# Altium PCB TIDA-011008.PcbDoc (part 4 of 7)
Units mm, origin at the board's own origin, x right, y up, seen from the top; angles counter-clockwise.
Board outline 252 x 205 mm, 4 copper layers (Top Layer, Inner Layer 1, Inner Layer 2, Bottom Layer), stack 1.926 mm thick; 517 components, 293 nets, 1426 pads, 1855 vias.
Unrouted connection lines stored in the file: 4.
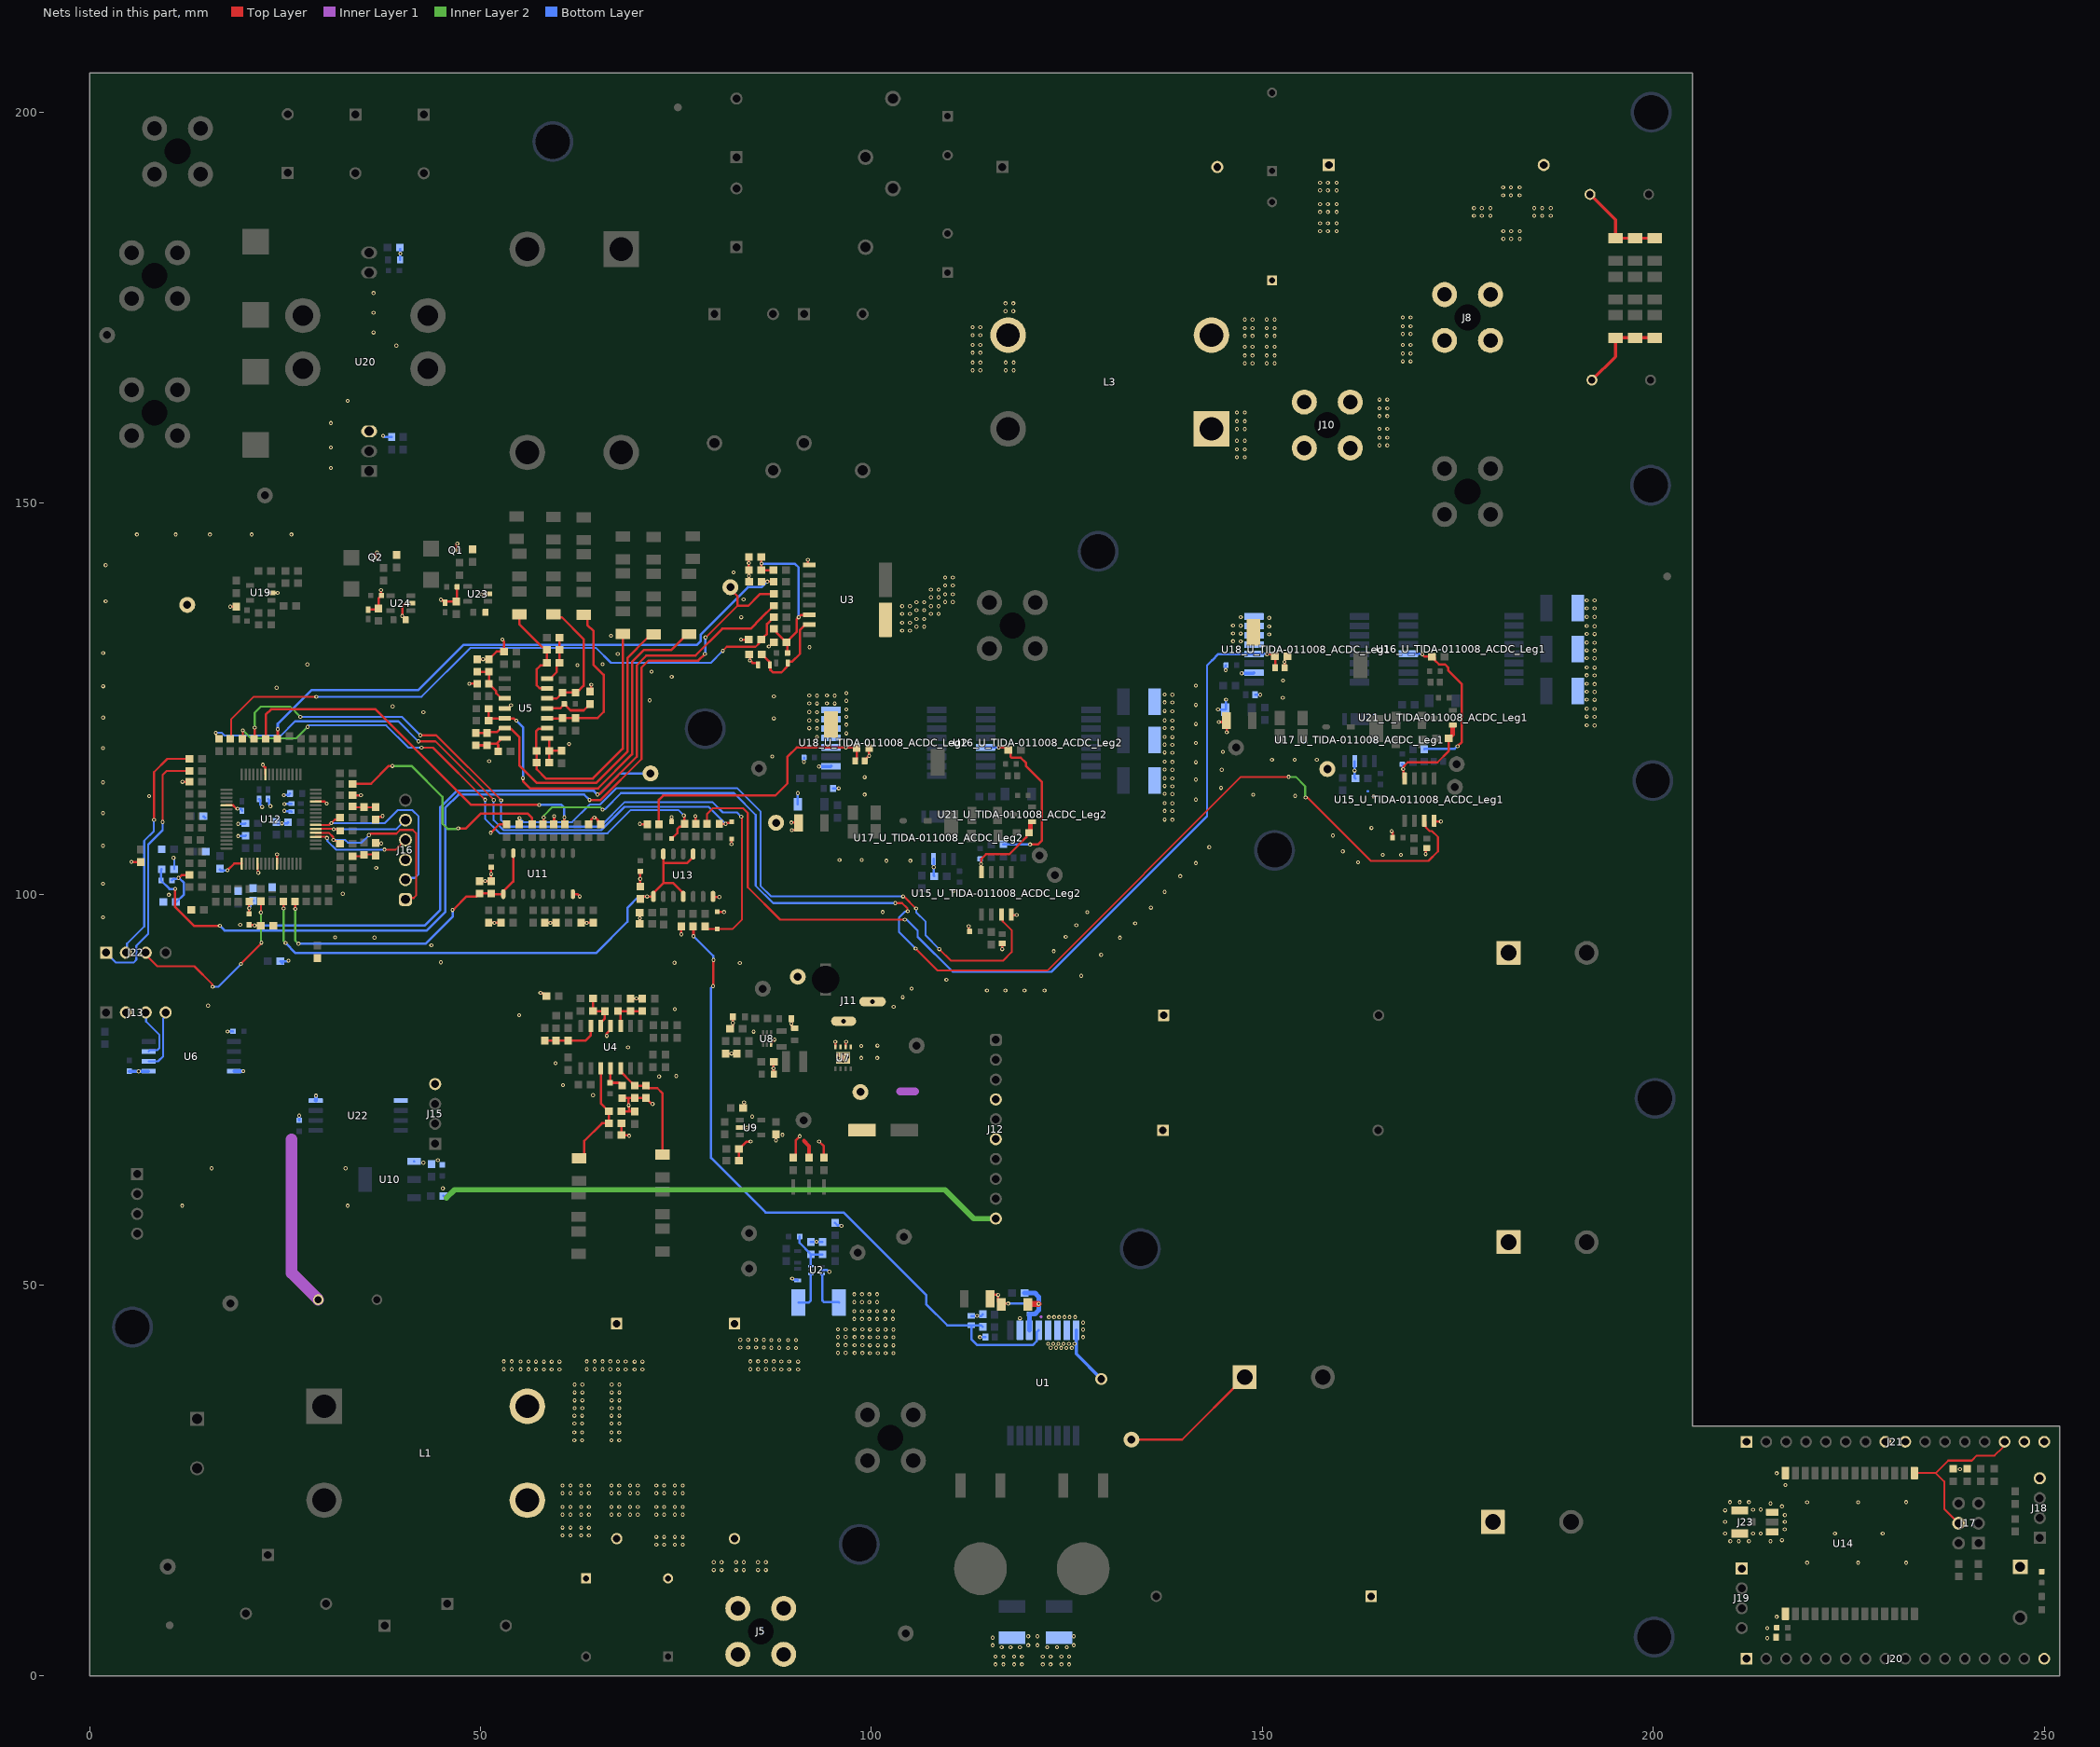
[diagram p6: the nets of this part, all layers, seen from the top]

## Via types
v1: diameter 0.508, hole 0.254, Top Layer to Bottom Layer, tented both sides, 1852 vias
v2: diameter 1.5/1.5/1.5/1.5 (per signal layer), hole 1, Top Layer to Bottom Layer, 2 vias
v3: diameter 0.508, hole 0.254, Top Layer to Bottom Layer, 1 vias

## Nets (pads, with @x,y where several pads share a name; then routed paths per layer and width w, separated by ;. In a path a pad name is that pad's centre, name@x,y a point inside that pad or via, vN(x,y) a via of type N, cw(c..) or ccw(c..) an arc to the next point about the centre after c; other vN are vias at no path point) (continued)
DC_Bus-: C1.1 C2.1 C3.1 C4.1 C5.1 C6.1 C7.2 C9.2 C10.2 C11.1 C14.1 C15.1 C16.1 C17.2 C18.2 C21.2 C22.2 C23.2 C28.1 C29.1 C32.1 C33.2 C34.2 C35.2 C36.2 C37.1 C38.1 C39.1 C40.2 C41.2 C42.1 C43.1 C44.2 C45.1 C46.2 C47.2 C48.1 C49.2 C53.1 C54.1 C55.1 C60.1 C61.1 C62.1 C65.2 C67.2 C69.2 C71.1 C72.1 C75.2 C76.2 C77.1 C78.1 C79.2 C80.2 C81.1 C82.2 C83.2 C84.1 C85.2 C86.2 C87.2 C88.2 C89.1 C90.2 C91.2 C92.1 C93.1 C94.1 C95.1 C96.2 C97.2 C98.2 C99.2 C100.2 C101.2 C102.2 C103.2 C104.2 C108_U_TIDA-011008_ACDC_Leg1.1 C108_U_TIDA-011008_ACDC_Leg2.1 C116_U_TIDA-011008_ACDC_Leg1.2 C116_U_TIDA-011008_ACDC_Leg2.2 C118_U_TIDA-011008_ACDC_Leg1.2 C118_U_TIDA-011008_ACDC_Leg2.2 C119_U_TIDA-011008_ACDC_Leg1.2 C119_U_TIDA-011008_ACDC_Leg2.2 C120_U_TIDA-011008_ACDC_Leg1.2 C120_U_TIDA-011008_ACDC_Leg2.2 C121_U_TIDA-011008_ACDC_Leg1.2 C121_U_TIDA-011008_ACDC_Leg2.2 C122_U_TIDA-011008_ACDC_Leg1.2 C122_U_TIDA-011008_ACDC_Leg2.2 C123_U_TIDA-011008_ACDC_Leg1.2 C123_U_TIDA-011008_ACDC_Leg2.2 C124_U_TIDA-011008_ACDC_Leg1.2 C124_U_TIDA-011008_ACDC_Leg2.2 C125_U_TIDA-011008_ACDC_Leg1.1 C125_U_TIDA-011008_ACDC_Leg2.1 C126_U_TIDA-011008_ACDC_Leg1.1 C126_U_TIDA-011008_ACDC_Leg2.1 C127_U_TIDA-011008_ACDC_Leg1.1 C127_U_TIDA-011008_ACDC_Leg2.1 C128.1 C129.1 C130.2 C132.1 C134.2 C135.2 C136.1 C137.2 C138.1 C139.1 C140.1 C141.1 D10.2 D11.2 D12.2 J11.2 J11.3 J12.4 J12.6 J16.3 Q1.2@46.898,143.989 Q2.2@36.614,143.095 R5.1 R7.2 R10.1 R28.1 R36.1 R37.1 R50.2 R51.1 R52.1 R53.2 R54.1 R83.2 R92.1 R93.1 R98.2 R99.1 R100.1 R104.1 R105.1 R106.1 R107.2 R128.1 R129.1 R130.1 R131.1 R137.2 R144.1 R161.2 R181_U_TIDA-011008_ACDC_Leg1.1 R181_U_TIDA-011008_ACDC_Leg2.1 R192.2 R193.2 TP2.1 TP5.1 TP23.1 TP24.1 TP31_U_TIDA-011008_ACDC_Leg1.1 TP31_U_TIDA-011008_ACDC_Leg2.1 TP32_U_TIDA-011008_ACDC_Leg1.1 TP32_U_TIDA-011008_ACDC_Leg2.1 U1.10 U1.13 U1.14 U1.15 U1.16 U2.2 U2.3 U3.3 U4.11 U5.11 U6.4 U7.5 U7.6 U7.7 U7.8 U7.9 U8.3 U9.2 U11.8 U12.5 U12.17 U12.21 U12.26 U12.45 U12.58 U13.7 U15_U_TIDA-011008_ACDC_Leg1.4 U15_U_TIDA-011008_ACDC_Leg2.4 U17_U_TIDA-011008_ACDC_Leg1.3 U17_U_TIDA-011008_ACDC_Leg2.3 U18_U_TIDA-011008_ACDC_Leg1.10 U18_U_TIDA-011008_ACDC_Leg1.13 U18_U_TIDA-011008_ACDC_Leg1.14 U18_U_TIDA-011008_ACDC_Leg1.15 U18_U_TIDA-011008_ACDC_Leg1.16 U18_U_TIDA-011008_ACDC_Leg2.10 U18_U_TIDA-011008_ACDC_Leg2.13 U18_U_TIDA-011008_ACDC_Leg2.14 U18_U_TIDA-011008_ACDC_Leg2.15 U18_U_TIDA-011008_ACDC_Leg2.16 U19.2 U20.3 U22.4 U23.2 U24.2 | length 220.6
  Top Layer w0.254: v1(17.989,136.774) 18.723,136.774 C130.2@18.747,136.75 ; U12.21@21.465,103.902 21.488,103.879 21.488,102.906 21.588,102.807 v1(21.588,102.74) ; U19.2@23.275,138.544 v1(24.058,138.544) ; Q2.2@36.614,143.095 36.616,143.097 36.616,143.501 36.769,143.654 v1(36.769,143.723) ; Q1.2@46.898,143.989 46.898,144.679 v1(47.039,144.819)
  Top Layer w0.3: v1(5.345,104.129) 6.527,104.129 C62.1@6.545,104.112 ; v1(11.881,114.37) 12.786,114.37 C102.2@12.79,114.365 ; C61.1@13.007,98.028 C61.1@13.035,97.999 ; U12.5@17.515,111.352 18.374,111.352 18.766,110.96 18.888,110.96 v1(18.927,110.922) ; v1(17.645,103.052) 18.495,103.902 U12.17@19.465,103.902 ; v1(22.155,116.555) 22.194,116.516 22.194,116.451 22.465,116.179 U12.58@22.465,115.302 ; U12.26@23.965,103.902 23.965,105.079 v1(23.978,105.092) ; U12.45@28.915,111.852 30.06,111.852 30.312,111.601 v1(30.328,111.601) ; R161.2@33.646,112.65 v1(34.717,112.65) ; C40.2@35.634,136.396 36.793,136.396 R36.1@36.951,136.554 36.951,137.809 37.32,138.178 C28.1@37.32,138.203 37.269,138.254 v1(37.269,138.891) ; R193.2@36.586,106.531 36.633,106.484 v1(37.311,106.484) ; R192.2@36.588,109.552 36.588,109.577 36.913,109.902 37.378,109.902 v1(37.478,110.002) ; C138.1@40.424,135.086 40.424,135.161 v1(40,135.586) 40,136.774 40.278,137.052 40.951,137.052 U24.2@41.101,137.202 ; v1(44.938,137.674) 44.978,137.634 45.111,137.634 45.227,137.518 45.327,137.518 45.477,137.368 C33.2@45.477,137.268 ; C33.2@45.627,137.426 R28.1@46.898,137.426 47.015,137.544 C29.1@47.015,139.306 ; v1(48.575,126.914) C43.1@49.598,126.914 ; R50.2@49.598,130.051 v1(50.323,130.051) 51.093,130.051 C45.1@51.098,130.056 51.098,130.081 52.06,131.043 C48.1@52.993,131.043 52.993,132.322 52.797,132.518 v1(52.797,132.572) ; C129.1@49.868,101.685 v1(50.593,101.685) R107.2@51.368,101.685 v1(51.368,102.572) C84.1@51.368,103.46 ; v1(50.12,138.362) 50.935,138.362 U23.2@50.965,138.393 ; R128.1@51.047,96.335 v1(51.772,96.335) C85.2@52.643,96.335 ; v1(51.317,107.852) 52.399,108.935 C83.2@53.368,108.935 ; U5.11@53.101,123.764 53.518,123.764 53.911,124.156 v1(53.911,124.164) ; v1(57.671,87.399) 57.728,87.399 57.825,87.301 58.096,87.301 C137.2@58.421,86.976 ; R129.1@58.253,96.335 v1(58.957,96.335) C86.2@59.682,96.335 ; C82.2@59.368,108.935 59.421,108.987 v1(59.421,109.965) ; v1@61.342,119.069 v1(61.342,119.208) ; U11.8@61.813,100.01 62.402,100.01 v1(62.706,99.706) ; R130.1@62.868,96.335 C87.2@64.406,96.335 ; R131.1@63.831,108.935 64.156,109.26 64.156,109.516 64.414,109.774 v1@64.53,109.774 ; C49.2@64.001,125.925 64.171,126.096 v1(64.171,126.796) ; v1(64.569,109.813) v1@64.53,109.774 ; C88.2@65.368,108.935 65.043,109.26 65.043,109.462 64.731,109.774 v1@64.53,109.774 ; v1(66.154,81.881) 66.154,82.182 66.654,82.682 U4.11@66.654,83.168 ; R51.1@68.024,70.718 R54.1@68.024,69.193 68.891,69.193 68.978,69.107 v1(69.032,69.107) ; C46.2@68.024,72.218 69.036,72.218 ; C42.1@68.104,73.918 68.829,73.918 ; R83.2@69.22,86.657 v1(69.945,86.657) C60.1@70.714,86.657 ; R53.2@69.761,72.218 69.036,72.218 ; C90.2@70.382,96.206 v1(70.382,96.931) R144.1@70.382,97.635 ; v1(70.382,108.989) 70.416,108.955 C96.2@71.319,108.955 ; R137.2@70.432,100.981 v1(70.432,101.956) C89.1@70.432,102.931 ; v1(72.016,73.176) 71.978,73.214 71.872,73.214 71.189,73.896 C47.2@71.189,73.921 R52.1@69.761,73.921 69.757,73.918 68.829,73.918 ; v1(74.442,109.85) 74.442,109.303 D11.2@74.452,109.294 ; C91.2@75.669,95.881 75.692,95.857 v1(75.692,94.864) ; v1(77.486,109.982) 77.519,109.949 C101.2@77.519,108.981 ; U13.7@79.742,99.706 79.817,99.631 v1(80.557,99.631) ; D10.2@80.288,97.742 81.125,97.742 v1(81.154,97.713) v1@81.183,97.685 ; C81.1@81.383,79.615 v1(82.108,79.615) 82.804,79.615 R106.1@82.808,79.619 ; R105.1@81.933,82.808 81.958,82.808 82.283,83.133 v1(82.283,83.533) C79.2@82.283,84.308 ; v1(82.108,106.393) 82.112,106.397 D12.2@82.112,107.081 ; C78.1@83.058,65.908 R104.1@83.058,67.408 83.083,67.408 83.993,68.319 84.518,68.319 v1(84.558,68.358) ; U9.2@83.183,70.158 v1(84.058,70.158) ; v1(83.328,132.562) 84.289,132.562 C38.1@84.295,132.568 ; C71.1@83.608,72.658 83.708,72.759 v1(83.708,73.383) ; v1(83.654,137.703) v1@83.684,137.703 ; C35.2@84.339,143.144 84.317,143.122 v1(84.317,142.335) 84.317,141.481 84.347,141.451 v1(84.347,140.705) C39.1@84.347,139.98 ; C41.2@84.378,130.685 84.46,130.602 v1(84.46,129.878) 84.515,129.878 84.81,129.583 85.41,129.583 85.51,129.483 R37.1@85.51,129.327 ; v1(86.885,131.682) 86.923,131.721 86.994,131.721 87.491,132.218 C34.2@87.516,132.218 ; U8.3@87.158,80.785 87.158,80.97 87.595,81.407 v1(87.628,81.407) ; C75.2@87.495,77.231 87.497,77.233 87.497,77.706 v1(87.479,77.725) 87.479,78.542 C77.1@87.52,78.583 ; v1(87.808,68.522) C72.1@87.808,69.272 ; v1(89.769,109.16) 90.676,109.16 C123_U_TIDA-011008_ACDC_Leg2.2@90.697,109.14 90.697,108.594 90.297,108.194 v1(89.812,108.194) ; C76.2@89.775,84.058 v1(89.775,83.433) 89.775,83.191 90.108,82.858 C80.2@90.183,82.858 ; R100.1@90.012,66.295 90.337,66.62 90.337,68.542 90.831,69.036 v1(90.831,69.043) ; v1(91.876,142.756) 91.876,142.236 92.026,142.086 U3.3@92.053,142.086 ; v1(93.311,68.373) 93.933,67.752 R98.2@93.933,66.295 ; v1(95.386,81.118) 95.408,81.096 U7.8@95.408,80.479 ; U7.6@96.708,80.479 96.708,81.062 v1(96.763,81.118) ; C127_U_TIDA-011008_ACDC_Leg2.1@99.14,117.053 99.14,117.128 v1(99.714,117.702) R181_U_TIDA-011008_ACDC_Leg2.1@99.714,118.683 ; v1(112.438,95.908) 112.438,95.362 C108_U_TIDA-011008_ACDC_Leg2.1@112.567,95.233 ; C9.2@115.175,48.275 115.175,48.576 115.374,48.775 116.176,48.775 v1(116.209,48.742) 116.215,48.736 116.215,47.925 C10.2@116.615,47.525 116.734,47.644 v1(117.501,47.644) ; v1(116.742,92.974) C116_U_TIDA-011008_ACDC_Leg2.2@116.742,93.708 ; U15_U_TIDA-011008_ACDC_Leg2.4@117.897,97.408 117.976,97.33 v1(118.581,97.33) ; TP2.1@133.049,30.25 TP2.1@133.266,30.25 139.75,30.25 C3.1@147.75,38.25 ; v1(144.444,122.018) 145.236,122.018 C123_U_TIDA-011008_ACDC_Leg1.2@145.416,122.198 145.455,122.159 v1(145.455,120.699) ; C127_U_TIDA-011008_ACDC_Leg1.1@152.844,128.95 v1(152.844,129.704) 152.844,130.075 152.848,130.079 152.848,130.104 153.173,130.429 R181_U_TIDA-011008_ACDC_Leg1.1@153.198,130.429 ; v1(166.547,108.052) 166.662,107.937 C108_U_TIDA-011008_ACDC_Leg1.1@166.662,107.229 ; v1(170.895,105.13) 170.895,105.771 C116_U_TIDA-011008_ACDC_Leg1.2@171.03,105.907 ; U15_U_TIDA-011008_ACDC_Leg1.4@171.992,109.404 172.101,109.295 v1(172.837,109.295) ; 68.829,73.918 68.956,73.792 v1(68.956,73.006) 68.994,72.967 68.994,72.508 69.036,72.467 69.036,72.218
  Top Layer w0.5: 91.372,68.455 91.372,68.453 92.034,67.791 R99.1@92.033,66.295
  Inner Layer 1 w0.4: 121.671,45.962 121.717,45.916
  Inner Layer 1 w1: 103.676,74.768 105.608,74.768
  Inner Layer 1 w1.5: 25.835,68.619 25.835,51.553 C7.2@29.25,48.138
  Bottom Layer w0.254: v1(10.74,104.636) 10.824,104.552 C37.1@10.824,103.203
  Bottom Layer w0.3: C54.1@14.574,109.965 C54.1@14.795,109.744 ; C128.1@16.665,103.165 16.778,103.052 v1(17.645,103.052) ; v1(17.656,82.451) 17.668,82.463 18.336,82.463 C65.2@18.348,82.475 ; v1(18.927,110.922) 18.965,110.884 19.354,110.884 19.504,110.734 C93.1@19.504,110.677 ; v1(19.014,107.434) 19.922,107.434 C98.2@19.965,107.477 ; v1(19.014,108.992) 19.876,108.992 C97.2@19.94,109.056 ; C100.2@21.665,112.177 21.815,112.027 21.815,111.474 22.083,111.206 v1(22.083,111.152) ; C92.1@22.84,112.177 22.99,112.027 22.99,111.457 23.14,111.307 v1(23.14,111.253) ; C103.2@23.895,109.215 24.047,109.064 v1(24.6,109.064) 25.264,109.064 C104.2@25.39,109.19 ; C120_U_TIDA-011008_ACDC_Leg2.2@24.676,91.145 C120_U_TIDA-011008_ACDC_Leg2.2@24.399,91.421 25.377,91.421 v1(25.443,91.487) ; v1(24.835,112.65) 24.873,112.688 25.447,112.688 C95.1@25.638,112.879 ; v1(24.896,110.665) 24.934,110.627 25.741,110.627 C99.2@25.815,110.552 ; v1(24.924,111.527) 24.949,111.552 25.79,111.552 C94.1@25.815,111.577 ; v1(26.808,71.685) 26.815,71.678 26.815,71.086 C67.2@26.822,71.079 ; v1(37.553,158.614) 37.607,158.614 37.766,158.454 C134.2@38.648,158.454 ; C135.2@39.717,181.11 39.731,181.125 39.731,181.908 v1(39.746,181.923) 39.746,182.489 C136.1@39.735,182.5 ; v1(89.862,50.857) 90.01,50.709 90.475,50.709 R10.1@90.575,50.609 ; C124_U_TIDA-011008_ACDC_Leg2.2@90.592,111.505 v1(90.592,112.93) ; v1(91.378,116.917) C125_U_TIDA-011008_ACDC_Leg2.1@91.378,117.486 ; C21.2@92.26,55.542 v1(92.985,55.542) C22.2@93.74,55.542 ; U2.3@93.74,51.442 93.733,51.442 93.733,48.044 93.95,47.827 95.829,47.827 R7.2@95.865,47.79 ; U2.2@93.74,51.942 94.331,51.942 94.562,51.711 v1(94.616,51.711) ; C126_U_TIDA-011008_ACDC_Leg2.1@95.1,113.539 v1(95.823,113.539) ; C23.2@95.35,57.992 95.35,57.967 95.675,57.642 96.056,57.642 96.115,57.583 v1(96.171,57.583) ; U17_U_TIDA-011008_ACDC_Leg2.3@107.97,104.508 v1(107.97,103.446) 107.97,102.384 C118_U_TIDA-011008_ACDC_Leg2.2@108.055,102.299 ; C15.1@112.775,46.075 v1(113.525,46.075) 114.05,46.075 R5.1@114.25,46.275 ; v1(113.887,43.35) C14.1@114.585,43.35 ; v1@117.48,47.623 v1(117.501,47.644) 117.523,47.666 C11.1@120.2,47.666 ; v1(144.34,123.623) C124_U_TIDA-011008_ACDC_Leg1.2@145.274,123.623 145.363,123.712 v1(145.363,124.879) ; v1(145.312,128.658) 145.312,129.228 C125_U_TIDA-011008_ACDC_Leg1.1@145.363,129.279 ; C126_U_TIDA-011008_ACDC_Leg1.1@149.078,125.527 149.098,125.507 v1(149.726,125.507) ; U17_U_TIDA-011008_ACDC_Leg1.3@161.814,117.004 161.814,114.88 C118_U_TIDA-011008_ACDC_Leg1.2@161.899,114.795 ; 163.499,113.195 163.524,113.195 ; v1@164.198,112.52 v1(164.207,112.52)
  Bottom Layer w0.4: v1(93.299,116.32) 93.319,116.339 94.811,116.339 U18_U_TIDA-011008_ACDC_Leg2.10@94.845,116.373 ; U1.16@126.2,44.25 126.2,41.201 v2(129.403,37.998) ; v1(147.364,128.245) 148.866,128.245 U18_U_TIDA-011008_ACDC_Leg1.10@148.938,128.317
  Bottom Layer w0.5: U6.4@18.515,77.359 18.523,77.367 19.67,77.367 v1(19.671,77.368) ; U22.4@28.93,73.605 28.963,73.638 v1(28.963,74.233)
  other v1: 115.875,1.505 116.875,1.505 118.25,1.505 119.25,1.505 121.925,1.505 122.925,1.505 124.3,1.505 125.3,1.505 115.875,2.5 116.875,2.5 118.25,2.5 119.25,2.5 121.925,2.5 122.925,2.5 124.3,2.5 125.3,2.5 116.665,3.702 117.801,3.702 119,3.702 122.5,3.702 123.75,3.702 125,3.702 115.5,3.953 120.064,3.953 121.25,3.953 125.875,3.953 115.5,4.923 120.064,5.1 121.25,5.1 125.875,5.1 99.817,41.308 100.817,41.308 101.826,41.307 102.826,41.307 97.851,41.328 98.851,41.328 95.714,41.342 96.714,41.342 124.936,41.974 122.938,41.99 123.611,41.994 124.264,41.98 125.629,41.98 99.817,42.303 100.817,42.303 101.826,42.302 102.826,42.302 97.851,42.323 98.851,42.323 95.714,42.338 96.714,42.338 122.612,42.496 123.273,42.496 123.925,42.496 124.585,42.496 125.26,42.496 125.983,42.496 99.817,43.331 100.817,43.331 101.826,43.329 102.826,43.329 95.714,43.365 96.714,43.365 97.851,43.351 98.851,43.351 127.075,43.35 99.817,44.326 100.817,44.326 101.826,44.325 102.826,44.325 127.071,44.314 95.714,44.36 96.714,44.36 97.851,44.346 98.851,44.346 127.075,45.215 97.8,45.674 98.8,45.674 99.734,45.674 100.734,45.674 101.763,45.674 102.763,45.674 119,45.76 122.707,45.916 123.368,45.916 124.02,45.916 124.68,45.916 125.355,45.916 126.079,45.916 97.8,46.67 98.8,46.67 99.734,46.67 100.734,46.67 101.763,46.67 102.763,46.67 97.801,47.839 98.801,47.839 99.737,47.839 100.737,47.839 97.801,48.834 98.801,48.834 99.737,48.834 100.737,48.834 88.623,69.223 84.745,71.564 64.397,74.307 60.546,75.576 72.849,76.691 75.051,76.743 59.604,78.384 96.383,78.579 98.692,79.058 100.751,79.058 95.758,79.079 97.008,79.079 96.383,79.579 68.87,80.404 98.692,80.586 100.772,80.636 84.942,82.419 54.95,84.512 74.859,85.313 102.841,85.594 15.161,85.741 103.996,86.829 114.784,87.684 117.143,87.684 119.588,87.684 122.146,87.684 105.156,87.915 109.598,89.043 126.839,89.563 83.183,91.192 74.815,91.226 44.942,91.297 129.384,92.25 123.317,92.709 43.723,93.468 131.785,94.439 36.437,94.451 31.414,94.483 124.853,94.547 126.214,96.029 19.278,96.089 133.739,96.269 63.606,96.321 1.719,97.057 101.449,97.713 127.614,97.705 135.75,98.277 10.142,99.925 32.384,100.06 137.5,100.288 110.483,100.423 1.719,101.321 139.5,102.307 36.669,103.374 141.5,103.978 162.25,104.064 101.927,104.272 104.983,104.272 95.92,104.382 98.764,104.382 165.405,105.038 167.723,105.038 160.298,105.475 143.218,106.008 1.719,106.191 159.024,107.505 163.96,108.472 138.496,109.517 137.501,109.544 1.719,110.37 138.496,110.625 137.501,110.652 138.496,111.625 137.501,111.652 141.5,112.096 7.634,112.536 154.194,112.578 148.85,112.713 99.14,112.742 138.496,112.805 137.501,112.833 144.718,113.595 138.496,113.805 137.501,113.833 1.719,114.294 141.5,114.662 138.496,114.805 137.501,114.833 99.14,114.97 161.808,115.803 144.815,115.908 138.496,115.914 137.501,115.941 141.5,116.878 138.496,116.914 137.501,116.941 51.098,117.001 151.24,117.187 154.151,117.2 156.968,117.2 87.322,117.616 138.496,118.096 137.501,118.124 144.952,118.212 1.719,118.693 138.496,119.096 137.501,119.124 141.5,119.331 93.048,120.094 138.496,120.096 137.501,120.124 96.789,120.571 93.048,121.202 138.496,121.204 92.053,121.229 137.501,121.232 192.495,121.577 191.5,121.605 96.789,121.679 141.5,121.761 93.048,122.202 138.496,122.204 92.053,122.229 137.501,122.232 87.521,122.481 1.735,122.586 96.789,122.679 192.495,122.686 191.5,122.713 42.708,123.275 93.048,123.275 92.053,123.303 138.496,123.404 137.501,123.432 96.789,123.62 192.495,123.686 191.5,123.713 38.773,124.009 141.5,124.207 93.048,124.383 95.31,124.383 92.053,124.411 94.315,124.411 138.496,124.513 137.501,124.54 96.789,124.729 71.633,124.789 192.495,124.866 191.5,124.893 152.614,125.108 87.521,125.29 93.048,125.383 95.31,125.383 92.053,125.411 94.315,125.411 138.496,125.513 137.501,125.54 96.789,125.729 192.495,125.866 191.5,125.893 23.918,126.397 1.735,126.589 141.5,126.662 192.495,126.866 191.5,126.893 152.65,127.334 74.459,127.801 192.495,127.974 191.5,128.001 71.871,128.451 192.495,128.974 191.5,129.001 62.41,129.297 27.863,129.384 65.63,129.415 192.495,130.157 191.5,130.184 67.561,130.728 1.735,130.839 192.495,131.157 191.5,131.184 92.082,131.593 192.495,132.157 191.5,132.184 147.247,132.326 146.252,132.354 66.691,133.043 150.884,133.234 192.495,133.265 191.5,133.292 147.247,133.326 146.252,133.354 150.884,134.234 192.495,134.265 191.5,134.292 147.247,134.326 146.252,134.354 150.884,135.342 83.35,135.41 147.247,135.435 191.5,135.465 192.495,135.465 191.5,136.573 192.495,136.573 2.056,137.444 191.5,137.573 192.495,137.573 82.385,141.144 2.056,142.075 6.05,146 11.006,146 15.4,146 20.727,146 25.821,146 30.867,154.5 30.867,157.119 30.867,160.25 33,163.079 39.248,170.158 36.329,171.837 36.329,174.369 36.329,176.882
Enable_DCAC: C129.2 R107.1 R145.2 U11.1 U11.15 | length 40.8
  Top Layer w0.3: R145.2@26.285,99.073 26.319,99.04 v1(26.319,98.128) ; v1(46.432,97.978) 46.488,97.978 46.592,98.082 46.613,98.082 48.237,99.706 49.49,99.706 49.518,99.735 49.543,99.735 49.868,100.06 C129.2@49.868,100.085 R107.1@51.368,100.085 51.443,100.01 U11.1@52.923,100.01 52.923,100.36 54.193,101.63 U11.15@54.193,105.26
  Inner Layer 2 w0.3: v1(26.319,98.128) 26.306,98.115 26.306,94.085 v1(26.727,93.664)
  Bottom Layer w0.3: v1(26.727,93.664) 42.985,93.664 46.432,97.111 v1(46.432,97.978)
Enable_DCDC: R137.1 R143.2 U13.1 U13.4 U13.10 U13.13 | length 72.1
  Top Layer w0.3: v1(24.81,98.166) R143.2@24.811,99.07 ; R137.1@70.432,99.381 70.757,99.706 v1(71.307,99.706) U13.1@72.122,99.706 72.122,100.131 73.392,101.401 ; U13.13@73.392,105.156 73.392,103.961 ; U13.4@75.932,99.706 75.932,100.131 74.662,101.401 73.392,101.401 ; U13.10@77.202,105.156 77.202,104.731 76.432,103.961 73.392,103.961 ; 73.392,101.401 73.392,103.961
  Inner Layer 2 w0.3: v1(24.81,98.166) 24.81,94.059 25.065,93.804 v1(25.065,93.75)
  Bottom Layer w0.3: v1(25.065,93.75) 26.356,92.46 64.766,92.46 68.783,96.476 68.783,98.25 70.24,99.706 v1(71.307,99.706)
FLT_1A: R115.1 U15_U_TIDA-011008_ACDC_Leg1.3 | length 156
  Top Layer w0.254: v1(103.045,98.865) 103.93,98.865 104.618,98.177 104.618,97.847 v1(104.645,97.82) ; v1@105.659,93.047 108.472,90.234 122.501,90.234 147.268,115.001 v1(153.373,115.001) ; v1(155.535,112.37) 155.786,112.37 163.896,104.26 171.249,104.26 172.464,105.475 172.464,107.306 171.718,108.052 171.423,108.052 170.895,108.58 170.895,109.231 U15_U_TIDA-011008_ACDC_Leg1.3@170.722,109.404
  Top Layer w0.3: R115.1@58.003,108.935 58.079,109.01 v1(58.079,109.803)
  Inner Layer 2 w0.254: v1(58.079,109.803) 58.126,109.85 58.126,110.073 59.177,111.125 65.32,111.125 v1(65.63,110.814) ; v1(153.373,115.001) 154.273,115.001 155.488,113.786 155.488,112.417 v1(155.535,112.37)
  Bottom Layer w0.254: v1(65.63,110.814) 65.677,110.861 65.91,110.861 67.98,112.93 82.423,112.93 85.21,110.143 85.21,101.084 87.43,98.865 v1(103.045,98.865) ; v1(104.645,97.82) 104.599,97.774 104.306,97.774 103.54,97.008 103.54,95.166 v1(105.659,93.048)
FLT_1A_mcu: R116.2 R123.2 | length 48.9
  Top Layer w0.3: R123.2@22.54,119.877 22.54,122.96 23.219,123.639 36.572,123.639 48.79,111.422 v1(57.51,111.422) ; v1(60.729,109.834) 60.729,108.999 R116.2@60.793,108.935
  Bottom Layer w0.3: v1(57.51,111.422) 57.514,111.426 60.359,111.426 60.729,111.056 v1(60.729,109.834)
FLT_1B: C127_U_TIDA-011008_ACDC_Leg1.2 R159.1 R181_U_TIDA-011008_ACDC_Leg1.2 U18_U_TIDA-011008_ACDC_Leg1.12 | length 118.7
  Top Layer w0.254: R159.1@78.979,108.981 78.979,110.246 79.742,111.009 83.566,111.009 84.183,110.392 84.183,100.892 88.325,96.75 v1(104.28,96.75)
  Top Layer w0.3: v1(150.609,130.697) 151.33,130.697 R181_U_TIDA-011008_ACDC_Leg1.2@151.598,130.429 ; C127_U_TIDA-011008_ACDC_Leg1.2@151.644,128.95 R181_U_TIDA-011008_ACDC_Leg1.2@151.644,130.497
  Bottom Layer w0.254: v1(104.28,96.75) 104.505,96.75 105.923,95.332 105.923,94.547 110.407,90.063 123.023,90.063 142.935,109.976 142.935,129.263 143.567,129.895
  Bottom Layer w0.3: 143.567,129.895 144.39,130.717 U18_U_TIDA-011008_ACDC_Leg1.12@148.938,130.717 ; U18_U_TIDA-011008_ACDC_Leg1.12@148.965,130.725 150.58,130.725 v1(150.609,130.697)
FLT_1B_mcu: D12.1 R122.2 R160.2 | length 78.2
  Top Layer w0.254: v1(16.131,120.627) 16.131,120.561 16.192,120.499 16.192,120.225 R122.2@16.54,119.877 ; v1(42.063,119.552) 44.242,119.552 51.703,112.092 v1(51.703,112.034)
  Top Layer w0.3: R160.2@80.554,108.981 80.561,108.989 v1(81.356,108.989) 81.41,108.989 81.552,109.131 81.962,109.131 D12.1@82.112,109.281
  Bottom Layer w0.254: v1(16.131,120.627) 16.935,120.627 17.283,120.279 24.458,120.279 26.286,122.106 39.509,122.106 v1(42.063,119.552) ; v1(51.703,112.034) 51.682,112.013 51.682,109.452 52.94,108.194 65.446,108.194 68.423,111.171 79.174,111.171 v1(81.356,108.989)
FLT_2A: R118.1 U15_U_TIDA-011008_ACDC_Leg2.3 | length 87.7
  Top Layer w0.254: v1@103.93,99.706 v1(104.055,99.706) 104.179,99.706 v1(105.722,98.164) ; v1(108.686,92.974) 110.159,91.5 116.842,91.5 117.942,92.6 117.942,95.388 116.8,96.53 116.8,97.235 U15_U_TIDA-011008_ACDC_Leg2.3@116.627,97.408
  Top Layer w0.3: R118.1@54.963,108.935 54.996,108.967 v1(54.996,109.725)
  Bottom Layer w0.254: v1(54.996,109.725) 55.504,109.216 61.716,109.216 63.97,111.47 65.275,111.47 67.345,113.539 82.86,113.539 85.814,110.585 85.814,101.084 87.192,99.706 v1(104.055,99.706) ; v1(105.722,98.164) 105.722,97.705 106.944,96.483 106.944,94.715 v1(108.686,92.974)
FLT_2A_mcu: R119.2 R124.2 | length 31.1
  Top Layer w0.3: R124.2@33.646,114.1 33.69,114.143 36.027,114.143 38.278,116.394 v1(38.738,116.394) ; v1(47.158,108.415) 48.146,108.415 50.058,110.328 56.02,110.328 56.618,109.729 R119.2@56.618,108.935
  Inner Layer 2 w0.3: v1(38.738,116.394) 41.177,116.394 45.146,112.425 45.146,109.002 45.796,108.352 47.095,108.352 v1(47.158,108.415)
FLT_2B: C127_U_TIDA-011008_ACDC_Leg2.2 R153.1 R181_U_TIDA-011008_ACDC_Leg2.2 U18_U_TIDA-011008_ACDC_Leg2.12 | length 36.8
  Top Layer w0.3: R153.1@72.83,108.955 72.83,112.087 73.359,112.616 87.706,112.616 89.27,114.181 89.27,117.583 90.446,118.758 v1(96.749,118.758) 96.787,118.796 97.851,118.796 R181_U_TIDA-011008_ACDC_Leg2.2@98.039,118.608 ; C127_U_TIDA-011008_ACDC_Leg2.2@97.94,117.053 98.114,117.227 R181_U_TIDA-011008_ACDC_Leg2.2@98.114,118.683
  Bottom Layer w0.3: U18_U_TIDA-011008_ACDC_Leg2.12@94.842,118.758 v1(96.749,118.758)
FLT_2B_mcu: D11.1 R125.2 R154.2 | length 71.1
  Top Layer w0.254: R125.2@19.54,119.877 19.615,119.952 v1(19.615,120.954) ; v1(42.463,118.738) 43.93,118.738 v1(50.588,112.081)
  Top Layer w0.3: D11.1@74.452,107.094 75.191,107.833 75.191,108.356 75.466,108.631 75.78,108.631 R154.2@76.105,108.956 ; v1(76.014,110.073) 76.105,109.982 R154.2@76.105,108.981
  Inner Layer 2 w0.254: v1(19.615,120.954) 20.617,119.952 26.453,119.952 v1(27.889,121.388)
  Bottom Layer w0.254: v1(27.889,121.388) 28.088,121.587 37.946,121.587 40.794,118.738 v1(42.463,118.738) ; v1(50.588,112.081) 50.588,109.642 52.439,107.79 66.254,107.79 69.231,110.767 75.32,110.767 v1(76.014,110.073)
FLT_A_LMG_U_TIDA-011008_ACDC_Leg1: R176_U_TIDA-011008_ACDC_Leg1.2 R177_U_TIDA-011008_ACDC_Leg1.2 U16_U_TIDA-011008_ACDC_Leg1.12 | length 21.2
  Top Layer w0.3: v1(170.47,130.679) 170.47,130.665 170.746,130.388 R177_U_TIDA-011008_ACDC_Leg1.2@171.718,130.388 ; R177_U_TIDA-011008_ACDC_Leg1.2@171.959,130.372 172.046,130.284 172.046,129.932 172.602,129.377 173.37,129.377 173.797,128.95 173.797,128.581 175.53,126.848 175.53,119.468 v1(174.968,118.906)
  Bottom Layer w0.3: U16_U_TIDA-011008_ACDC_Leg1.12@168.687,130.754 170.341,130.754 170.416,130.679 v1(170.47,130.679) ; R176_U_TIDA-011008_ACDC_Leg1.2@170.722,118.55 170.761,118.589 174.594,118.589 174.911,118.906 v1(174.968,118.906)
FLT_A_LMG_U_TIDA-011008_ACDC_Leg2: R176_U_TIDA-011008_ACDC_Leg2.2 R177_U_TIDA-011008_ACDC_Leg2.2 U16_U_TIDA-011008_ACDC_Leg2.12 | length 22.3
  Top Layer w0.3: v1(116.301,118.758) 117.197,118.758 117.783,118.172 117.783,117.625 117.959,117.449 119.122,117.449 119.75,116.821 119.75,116.394 121.815,114.329 121.815,106.875 121.301,106.362 v1(120.298,106.362)
  Bottom Layer w0.3: U16_U_TIDA-011008_ACDC_Leg2.12@114.592,118.758 v1(116.301,118.758) ; R176_U_TIDA-011008_ACDC_Leg2.2@116.861,106.396 116.894,106.362 v1(120.298,106.362)
FLT_Boost: C15.2 R5.2 R150.1 U1.12 | length 87.4
  Top Layer w0.3: R150.1@77.169,95.881 77.245,95.805 v1(77.245,94.628) ; v1(79.742,88.25) 79.779,88.287 79.779,91.555 v1(79.816,91.592)
  Bottom Layer w0.3: v1(77.245,94.628) 79.778,92.096 79.778,91.63 v1(79.816,91.592) ; v1(79.742,88.25) 79.5,88.008 79.5,66.272 86.477,59.295 96.449,59.295 107,48.743 107,47.575 109.7,44.875 C15.2@112.775,44.875 ; R5.2@114.25,44.675 114.05,44.875 C15.2@112.775,44.875 ; U1.12@121.4,44.25 121.139,43.989 121.139,42.83 120.647,42.338 113.539,42.338 112.775,43.102 C15.2@112.775,44.875
FLT_Boost_mcu: D10.1 R121.2 R151.2 | length 94.4
  Top Layer w0.254: R121.2@21.04,119.877 21.127,119.963 v1(21.127,121.317) ; v1(42.322,120.313) 44.347,120.313 v1(52.643,112.017) ; R151.2@79.044,95.542 D10.1@80.288,95.542 82.242,95.542 83.423,96.723 v1@83.423,109.843
  Top Layer w0.3: R151.2@78.719,95.881 78.719,95.867 R151.2@79.044,95.542 ; v1(83.358,109.908) v1@83.423,109.843
  Inner Layer 2 w0.254: v1(21.127,121.317) 21.127,123.205 21.921,124 25.633,124 v1(26.965,122.667)
  Bottom Layer w0.254: v1(26.965,122.667) 39.968,122.667 v1(42.322,120.313) ; v1(52.643,112.017) 52.643,109.46 53.465,108.639 65.32,108.639 68.468,111.788 79.671,111.788 81.008,110.45 82.816,110.45 v1(83.358,109.908)
GND_WiFi: C66.1 C68.1 C73.1 C74.1 C105.1 C106.1 C107.1 J12.10 J13.2 J15.4 J18.4 J19.1 J20.1 J20.16 J21.1 J21.8 J21.9 J21.15 J21.16 J23.2@211.07,18.25 J23.3@211.07,21.2 R165.1 R166.1 SW1.1 U6.5 U10.1 U14.1 U14.28 U14.29 U14.31 U22.5 | length 74.9
  Inner Layer 2 w0.7: 45.635,61.154 46.68,62.2 109.4,62.2 113.087,58.512 J12.10@115.917,58.512
  Bottom Layer w0.3: U10.1@41.512,65.814 U10.1@41.519,65.822 ; C73.1@45.277,61.408 C73.1@45.395,61.289
  Bottom Layer w0.4: C66.1@5.093,77.36 5.101,77.353 6.275,77.353 v1(6.283,77.345) U6.5@7.56,77.345
  other v1: 214.594,4.855 214.594,6.145 215.8,7.59 219.687,14.5 226.219,14.5 232.358,14.5 209.855,17.25 210.963,17.25 212.245,17.25 215.016,17.25 216.462,17.386 209.188,18.225 212.765,18.225 213.74,18.225 223.25,18.225 229.353,18.225 216.821,18.77 209.188,19.725 216.832,19.725 216.832,20.587 209.188,21.2 212.765,21.281 213.74,21.31 216.462,21.714 215.016,22.09 219.687,22.218 226.219,22.218 209.808,22.25 211.07,22.25 212.245,22.25 232.358,22.25 216.91,24.438 215.8,25.945 239.24,26.472 11.84,60.164 33,60.164 45.194,62.382 15.611,64.935 32.746,64.935 42.706,65.651 44.549,65.998
GPIO24: R189.2 R191.1 R193.1 | length 3.1
  Top Layer w0.254: R189.2@33.656,104.856 34.717,104.856 34.938,105.077 35.088,105.077 36.44,105.077 R193.1@36.586,104.931
GPIO28: J22.1 R185.2 | length 33.2
  Top Layer w0.254: v1(9.346,109.24) 9.346,115.249 9.865,115.769 R185.2@12.79,115.769
  Bottom Layer w0.254: J22.1@2.11,92.516 3.38,91.246 5.605,91.246 5.974,91.614 5.974,93.405 7.5,94.931 7.5,106.335 9.346,108.181 v1(9.346,109.24)
GPIO29: J22.2 R182.2 | length 29.8
  Top Layer w0.254: v1(8.244,109.505) 8.244,115.613 9.949,117.319 R182.2@12.79,117.319
  Bottom Layer w0.254: J22.2@4.65,92.516 4.794,92.659 4.794,93.672 6.998,95.876 6.998,106.837 8.226,108.065 8.226,109.487 v1(8.244,109.505)
GPIO32: R183.2 R190.1 R192.1 | length 3
  Top Layer w0.254: R183.2@33.646,111.25 33.794,111.102 35.088,111.102 36.538,111.102 R192.1@36.588,111.152
GPIO227: J22.3 R186.2 | length 24.6
  Top Layer w0.254: J22.3@7.19,92.516 7.19,92.272 8.68,90.783 13.397,90.783 15.7,88.48 15.7,88.202 v1(15.749,88.153) ; v1(19.358,91.07) 19.358,91.116 22,93.758 v1(22,93.804) ; v1(21.908,97.664) R186.2@21.908,99.084
  Inner Layer 2 w0.254: v1(21.908,97.664) 21.908,93.896 v1(22,93.804)
  Bottom Layer w0.254: v1(15.749,88.153) 15.761,88.165 16.453,88.165 v1(19.358,91.07)
GPRS_RX: J13.4 U6.6 | length 7.9
  Bottom Layer w0.254: U6.6@7.56,78.615 8.761,78.615 9.427,79.28 9.427,84.082 9.482,84.137 9.482,84.631 J13.4@9.73,84.879
GPRS_TX: J13.3 U6.7 | length 6.8
  Bottom Layer w0.254: J13.3@7.19,84.879 7.238,84.831 7.238,83.723 8.95,82.011 8.95,80.35 8.658,80.058 7.733,80.058 U6.7@7.56,79.885
IAC_F\A\U\L\T\: C39.2 R33.2 R127.2 | length 74.1
  Top Layer w0.3: R127.2@24.04,119.877 24.073,119.91 v1(24.073,121.099) ; C39.2@85.947,139.98 v1(86.697,139.98) R33.2@87.495,139.98
  Bottom Layer w0.3: v1(24.073,121.099) 24.073,121.785 28.402,126.114 42.063,126.114 47.856,131.907 77.7,131.907 78.145,132.352 78.145,133.187 84.213,139.255 85.972,139.255 v1(86.697,139.98)
IAC_O\C\: C38.2 R32.2 R126.2 | length 79.8
  Top Layer w0.254: R126.2@18.015,119.877 18.13,119.991 18.13,122.392 20.988,125.25 v1(29,125.25) ; v1(80.99,131.118) 81.512,131.639 85.192,131.639 85.645,132.093 85.645,132.318 C38.2@85.895,132.568
  Top Layer w0.3: C38.2@85.92,132.568 86.245,132.893 86.245,132.903 86.639,133.297 86.639,134.559 87.496,135.415 R32.2@87.521,135.415
  Bottom Layer w0.254: v1(29,125.25) 42.463,125.25 48.694,131.48 64.8,131.48 66.691,129.589 79.482,129.589 v1@80.99,131.098
IAC_OUT: C141.2 FB2.2 R132.2 | length 2.8
  Top Layer w0.3: FB2.2@20.406,97.487 20.412,97.493 20.412,98.192 v1(20.418,98.198) 20.418,99.022 R132.2@20.463,99.066
  Bottom Layer w0.3: v1(20.418,98.198) 20.418,98.254 20.613,98.449 20.613,98.855 C141.2@20.938,99.18
IAC_REF: C140.2 FB3.2 R133.2 | length 6.1
  Top Layer w0.3: v1@11.356,102.081 11.413,102.081 11.771,102.44 R133.2@12.79,102.44
  Bottom Layer w0.3: FB3.2@10.54,101.757 10.74,101.957 v1@11.176,101.957 ; C140.2@11.044,98.983 11.069,98.983 12.073,99.987 12.073,101.432 11.424,102.081 v1(11.384,102.081)
LDO5V_SN_U_TIDA-011008_ACDC_Leg1: C19_U_TIDA-011008_ACDC_Leg1.1 C109_U_TIDA-011008_ACDC_Leg1.2 U15_U_TIDA-011008_ACDC_Leg1.8 U21_U_TIDA-011008_ACDC_Leg1.1 | length 12.4
  Top Layer w0.3: U15_U_TIDA-011008_ACDC_Leg1.8@168.182,114.804 168.051,114.936 168.051,115.962 v1(168.012,116) 168.051,116.038 168.051,116.312 168.601,116.862 172.411,116.862 173.833,118.285 C19_U_TIDA-011008_ACDC_Leg1.1@173.833,119.922
  Top Layer w0.6: C19_U_TIDA-011008_ACDC_Leg1.1@173.833,119.922 173.858,119.922 174.367,120.431 U21_U_TIDA-011008_ACDC_Leg1.1@174.367,121.631
  Bottom Layer w0.3: C109_U_TIDA-011008_ACDC_Leg1.2@167.912,116.6 168.012,116.5 v1(168.012,116)
LDO5V_SN_U_TIDA-011008_ACDC_Leg2: C19_U_TIDA-011008_ACDC_Leg2.1 C109_U_TIDA-011008_ACDC_Leg2.2 U15_U_TIDA-011008_ACDC_Leg2.8 U21_U_TIDA-011008_ACDC_Leg2.1 | length 11.7
  Top Layer w0.3: U15_U_TIDA-011008_ACDC_Leg2.8@114.072,102.823 114.062,102.834 114.062,103.844 v1(114.036,103.87) 114.074,103.908 114.074,104.526 114.667,105.119 117.642,105.119 119.817,107.294 119.817,107.537 120.142,107.862 C19_U_TIDA-011008_ACDC_Leg2.1@120.167,107.862
  Top Layer w0.6: C19_U_TIDA-011008_ACDC_Leg2.1@120.167,107.862 120.192,107.862 120.367,108.037 120.367,109.265 U21_U_TIDA-011008_ACDC_Leg2.1@120.567,109.265
  Bottom Layer w0.3: C109_U_TIDA-011008_ACDC_Leg2.2@113.917,104.508 113.998,104.428 113.998,103.908 v1(114.036,103.87)
LOGGER: J17.4 J21.14 U14.15 | length 21.1
  Top Layer w0.254: U14.15@233.42,25.975 236.134,25.975 ; J17.4@239.065,19.55 237.226,21.389 237.226,24.883 236.134,25.975 ; J21.14@244.94,29.975 244.702,29.737 244.702,29.25 243.661,28.209 241.395,28.209 240.758,27.571 237.73,27.571 236.134,25.975
MCU_TCK: J16.4 U12.36 | length 12.9
  Top Layer w0.254: U12.36@28.915,107.352 30.145,107.352 30.301,107.196 v1(30.368,107.196) ; v1(37.713,105.706) 39.168,105.706 J16.4@40.399,106.937
  Bottom Layer w0.254: v1(30.368,107.196) 30.416,107.148 30.416,106.808 31.519,105.706 v1(37.713,105.706)
MCU_TDI: J16.2 R156.1 U12.39 | length 25.6
  Top Layer w0.254: U12.39@28.915,108.852 30.632,108.852 30.866,109.086 v1(30.932,109.086) 31.378,109.532 31.769,109.532 R156.1@32.045,109.808 32.07,109.808 R156.1@32.418,109.46
  Bottom Layer w0.254: v1(30.932,109.086) 37.745,109.086 39.398,110.739 41.293,110.739 42.085,109.947 42.085,102.56 41.605,102.08 40.623,102.08 J16.2@40.399,101.857
MCU_TDO: J16.1 R157.1 U12.37 | length 25
  Top Layer w0.254: U12.37@28.915,107.852 30.6,107.852 31.161,107.291 31.161,106.978 v1(31.197,106.942) 31.264,106.942 31.396,106.81 31.699,106.81 R157.1@32.047,106.462 ; v1(35.724,107.565) 35.79,107.565 35.966,107.741 39.242,107.741 39.727,108.226 41.349,108.226 41.757,107.817 41.757,99.824 41.456,99.523 40.635,99.523 J16.1@40.414,99.302
  Bottom Layer w0.254: v1(31.197,106.942) 32.692,106.942 33.043,106.591 34.795,106.591 35.724,107.52 v1(35.724,107.565)
MCU_TMS: J16.5 R155.1 U12.38 | length 12.9
  Top Layer w0.254: U12.38@28.915,108.352 31.207,108.352 v1(31.238,108.321) 31.84,108.321 R155.1@32.059,108.102
  Bottom Layer w0.254: v1(31.238,108.321) 39.243,108.321 J16.5@40.399,109.477
NetC8_2: C8.2 C12.2 C13.2 J5.1 L1.3
  other v1: 79.842,13.571 80.837,13.571 82.69,13.571 83.685,13.571 85.505,13.571 86.5,13.571 79.842,14.571 80.837,14.571 82.69,14.571 83.685,14.571 85.505,14.571 86.5,14.571 72.49,16.811 73.49,16.811 74.865,16.811 75.865,16.811 72.49,17.807 73.49,17.807 74.865,17.807 75.865,17.807 60.5,18 61.5,18 62.875,18 63.875,18 60.5,18.995 61.5,18.995 62.875,18.995 63.875,18.995 60.5,20.646 61.5,20.646 62.875,20.646 63.875,20.646 66.75,20.646 67.75,20.646 69.125,20.646 70.125,20.646 72.49,20.646 73.49,20.646 74.865,20.646 75.865,20.646 60.5,21.641 61.5,21.641 62.875,21.641 63.875,21.641 66.75,21.641 67.75,21.641 69.125,21.641 70.125,21.641 72.49,21.641 73.49,21.641 74.865,21.641 75.865,21.641 60.5,23.393 61.5,23.393 62.875,23.393 63.875,23.393 66.75,23.393 67.75,23.393 69.125,23.393 70.125,23.393 72.49,23.393 73.49,23.393 74.865,23.393 75.865,23.393 60.5,24.388 61.5,24.388 62.875,24.388 63.875,24.388 66.75,24.388 67.75,24.388 69.125,24.388 70.125,24.388 72.49,24.388 73.49,24.388 74.865,24.388 75.865,24.388
NetC10_1: C10.1 C11.2 R1.2 U1.11 | length 8.6
  Top Layer w0.6: C10.1@120.015,47.525 C10.1@120.1,47.61
  Top Layer w0.8: C10.1@120.1,47.61 v1(121.4,47.61)
  Bottom Layer w0.6: R1.2@119.59,49 120.931,49 121.4,48.531 v1(121.4,47.61) 121.4,46.788 120.928,46.316 C11.2@120.2,46.316 U1.11@120.2,44.25
NetC12_1: C12.1 C13.1 C20.1 L1.4 R7.1 U2.4 | length 5.1
  Bottom Layer w0.3: R7.1@90.665,47.79 92.007,47.79 92.26,48.044 U2.4@92.26,51.442
  other v1: 62,30.167 62.995,30.167 66.75,30.167 67.745,30.167 62,31.167 62.995,31.167 66.75,31.167 67.745,31.167 62.014,32.304 63.01,32.304 66.764,32.304 67.76,32.304 62.014,33.304 63.01,33.304 66.764,33.304 67.76,33.304 62.034,34.27 63.03,34.27 66.784,34.27 67.78,34.27 62.034,35.27 63.03,35.27 66.784,35.27 67.78,35.27 62.036,36.279 63.031,36.279 66.786,36.279 67.781,36.279 62.036,37.279 63.031,37.279 66.786,37.279 67.781,37.279 57.097,39.22 58.097,39.22 59.106,39.219 60.106,39.219 69.714,39.219 70.714,39.219 90.623,39.219 52.994,39.255 53.994,39.255 55.132,39.24 56.132,39.24 63.602,39.255 64.602,39.255 65.611,39.253 66.611,39.253 67.577,39.234 68.577,39.234 84.511,39.255 85.511,39.255 86.52,39.253 87.52,39.253 88.486,39.234 89.486,39.234 57.097,40.216 58.097,40.216 59.106,40.214 60.106,40.214 69.714,40.214 70.714,40.214 90.623,40.214 55.132,40.236 56.132,40.236 67.577,40.229 68.577,40.229 88.486,40.229 89.486,40.229 52.994,40.25 53.994,40.25 63.602,40.25 64.602,40.25 65.611,40.249 66.611,40.249 84.511,40.25 85.511,40.25 86.52,40.249 87.52,40.249 87.214,41.989 88.214,41.989 89.351,41.974 90.351,41.974 83.239,42.01 84.239,42.01 85.248,42.009 86.248,42.009 87.214,42.984 88.214,42.984 89.351,42.97 90.351,42.97 83.239,43.005 84.239,43.005 85.248,43.004 86.248,43.004
NetC21_1: C21.1 C22.1 FB1.2 U2.6 | length 5.8
  Bottom Layer w0.3: FB1.2@90.825,56.215 90.825,55.402 92.26,53.967 C21.1@92.26,53.942 ; U2.6@92.26,52.442 C21.1@92.26,53.942 ; C22.1@93.74,53.942 C21.1@92.26,53.942
NetC24_1: C24.1 C27.2 L3.3 U3.1
  other v1: 103.933,133.715 104.928,133.715 105.765,134.207 106.76,134.207 103.933,134.715 104.928,134.715 105.765,135.207 106.76,135.207 103.933,135.839 104.928,135.839 107.618,135.837 108.613,135.837 105.765,136.331 106.76,136.331 103.933,136.839 104.928,136.839 107.618,136.837 108.613,136.837 105.765,137.331 106.76,137.331 109.422,137.365 110.418,137.365 107.618,137.961 108.613,137.961 109.422,138.365 110.418,138.365 107.618,138.961 108.613,138.961 109.422,139.489 110.418,139.489 109.422,140.489 110.418,140.489 112.939,167 113.934,167 117.187,167 118.183,167 112.939,168 113.934,168 117.187,168 118.183,168 112.939,169.25 113.934,169.25 112.939,170.25 113.934,170.25 112.939,171.5 113.934,171.5 112.939,172.5 113.934,172.5 117.158,174.564 118.154,174.564 117.158,175.564 118.154,175.564
NetC25_2: C25.2 C26.2 J8.1 L3.2 R14.2 R15.2 R16.2 | length 11.9
  Top Layer w0.4: C25.2@191.915,189.5 195.165,186.25 R16.2@195.165,183.9 R15.2@197.665,183.9 R14.2@200.165,183.9
  other v1: 147.75,167.892 148.745,167.892 150.579,167.892 151.574,167.892 167.973,168.142 168.968,168.142 147.75,168.892 148.745,168.892 150.579,168.892 151.574,168.892 167.973,169.142 168.968,169.142 147.75,170 148.745,170 150.579,170 151.574,170 167.973,170.25 168.968,170.25 147.75,171.392 148.745,171.392 150.579,171.392 151.574,171.392 167.973,171.642 168.968,171.642 147.75,172.392 148.745,172.392 150.579,172.392 151.574,172.392 167.973,172.642 168.968,172.642 147.75,173.5 148.745,173.5 150.579,173.5 151.574,173.5 167.973,173.75 168.968,173.75 180.828,183.805 181.828,183.805 182.936,183.805 180.828,184.8 181.828,184.8 182.936,184.8 177.077,186.75 178.077,186.75 179.185,186.75 184.791,186.75 185.791,186.75 186.9,186.75 177.077,187.745 178.077,187.745 179.185,187.745 184.791,187.745 185.791,187.745 186.9,187.745 180.807,189.391 181.807,189.391 182.915,189.391 180.807,190.386 181.807,190.386 182.915,190.386
NetC26_1: C26.1 C31.1 J10.1 L3.1 R21.1 R22.1 R23.1 | length 11.6
  Top Layer w0.4: C31.1@192.165,165.75 195.165,168.75 R23.1@195.165,171.15 R22.1@197.665,171.15 R21.1@200.165,171.15
  other v1: 146.755,155.892 147.75,155.892 146.755,156.892 147.75,156.892 164.992,157.392 165.987,157.392 146.755,158 147.75,158 164.992,158.392 165.987,158.392 146.755,159.487 147.75,159.487 164.992,159.5 165.987,159.5 146.755,160.487 147.75,160.487 164.992,161.142 165.987,161.142 146.755,161.595 147.75,161.595 164.992,162.142 165.987,162.142 164.992,163.25 165.987,163.25 157.392,184.8 158.392,184.8 159.5,184.8 157.392,185.795 158.392,185.795 159.5,185.795 157.392,187.25 158.392,187.25 159.5,187.25 157.392,188.245 158.392,188.245 159.5,188.245 157.392,190 158.392,190 159.5,190 157.392,190.995 158.392,190.995 159.5,190.995
NetC32_2: C32.2 FB2.1 R26.2 TP13.1 | length 107.6
  Top Layer w0.3: FB2.1@20.406,96.087 20.446,96.047 21.071,96.047 v1(21.111,96.007) 21.864,96.007 C32.2@21.898,95.973 ; v1(64.966,112.743) v1@65.004,112.782 ; v1@65.19,112.782 70,117.591 70,129.29 71.222,130.512 77.486,130.512 80.933,133.959 84.564,133.959 85.895,135.29 87.496,136.89 R26.2@87.521,136.89
  Bottom Layer w0.3: v1(21.111,96.007) 21.135,95.982 42.868,95.982 44.867,97.981 44.867,111.116 46.963,113.213 64.497,113.213 v1(64.966,112.743) 65.004,112.782 65.192,112.782 67.854,115.444 TP13.1@71.757,115.444
NetC34_1: C34.1 C35.1 C36.1 FB4.2 R29.2 R30.2 U3.8 | length 23.7
  Top Layer w0.3: C36.1@85.932,141.451 85.937,141.446 R29.2@87.477,141.446 ; C36.1@85.939,141.458 85.941,141.46 85.941,143.141 C35.1@85.939,143.144 ; R30.2@87.521,133.959 87.546,133.959 87.871,133.634 87.871,133.463 88.766,132.568 88.766,132.543 89.27,132.038 FB4.2@89.27,130.855 ; C34.1@89.141,132.218 89.466,132.543 89.466,132.568 90.424,133.526 90.424,135.136 v1(90.698,135.411) 90.972,135.685 92.001,135.685 U3.8@92.053,135.736
  Bottom Layer w0.3: v1(85.941,142.283) 85.974,142.25 90.232,142.25 90.698,141.784 v1(90.698,135.411)
NetC37_2: C37.2 FB3.1 R31.1 TP14.1 | length 120.8
  Top Layer w0.3: v1(10.95,100.67) 10.95,98.366 13.36,95.956 v1(16.665,95.956) ; v1@63.962,112.045 65.359,112.045 70.594,117.28 70.594,128.977 71.489,129.872 77.856,129.872 v1(78.712,130.728) ; v1(78.778,132.834) 78.825,132.834 82.881,136.89 ; TP14.1@81.962,139.255 81.962,139.021 82.881,138.101 82.881,136.89 ; R31.1@87.527,138.39 85.758,138.39 85.582,138.215 84.258,136.89 82.881,136.89
  Bottom Layer w0.3: C37.2@9.224,103.203 9.14,103.119 FB3.1@9.14,101.757 10.227,100.67 v1(10.95,100.67) ; v1(16.665,95.956) 17.255,95.367 43.131,95.367 45.478,97.714 45.478,111.037 47.18,112.74 63.268,112.74 v1(63.958,112.05) ; v1@78.745,130.761 v1@78.745,132.801
NetC41_1: C41.1 R35.1 R37.2 U3.9 | length 12.2
  Top Layer w0.3: C41.1@85.978,130.685 86.003,130.685 86.91,129.777 86.91,129.427 R37.2@87.01,129.327 87.081,129.256 87.081,128.691 87.415,128.357 88.485,128.357 89.22,129.092 89.22,129.485 R35.1@89.32,129.585 89.32,129.621 89.42,129.721 89.845,129.721 90.878,130.754 90.878,133.816 91.528,134.466 U3.9@92.053,134.466
NetC42_2: C42.2 FB5.1 U4.4 | length 3.6
  Top Layer w0.3: FB5.1@66.579,75.877 66.617,75.914 66.617,77.681 U4.4@66.654,77.718
  Top Layer w0.4: FB5.1@66.579,75.877 67.77,75.877 68.104,75.543 C42.2@68.104,75.518
NetC45_2: C45.2 R38.2 R50.1 U5.10 | length 6
  Top Layer w0.3: R50.1@49.598,128.451 49.603,128.456 C45.2@51.098,128.456 R38.2@51.098,126.914 51.098,126.889 52.021,125.966 52.021,125.689 52.676,125.034 U5.10@53.101,125.034
NetC46_1: C46.1 R45.2 R51.2 U4.3 | length 14.1
  Top Layer w0.3: R45.2@62.619,66.382 62.97,66.382 63.27,66.682 63.27,68.432 65.556,70.718 R51.2@66.424,70.718 C46.1@66.424,72.218 66.399,72.218 65.384,73.233 U4.3@65.384,77.718
NetC47_1: C47.1 R48.2 R52.2 U4.5 | length 14.6
  Top Layer w0.3: U4.5@67.924,77.718 67.924,77.293 69.346,75.871 69.436,75.871 69.761,75.546 R52.2@69.761,75.521 C47.1@71.189,75.521 71.189,75.518 71.514,75.193 72.621,75.193 73.256,74.558 R48.2@73.256,66.832
NetC49_1: C49.1 FB6.2 U5.4 | length 6.4
  Top Layer w0.3: U5.4@58.551,123.764 60.192,123.764 60.527,124.099 60.527,124.132 FB6.2@60.727,124.332 60.927,124.132 60.927,124.095 61.512,123.509 63.21,123.509 64.001,124.3 C49.1@64.001,124.325
NetC50_1: C50.1 R55.1 R60.2 U5.3 | length 21
  Top Layer w0.3: U5.3@58.551,122.494 60.43,122.494 R55.1@60.476,122.54 62.141,122.54 C50.1@62.154,122.526 64.979,122.526 65.75,123.297 65.75,128.043 64.476,129.317 64.476,133.634 63.676,134.434 63.676,135.302 63.376,135.602 R60.2@63.221,135.602
NetC51_1: C51.1 R56.1 R63.2 U5.5 | length 16.4
  Top Layer w0.3: U5.5@58.551,125.034 59.755,125.034 60.476,125.755 R56.1@60.476,125.78 C51.1@62.154,125.78 62.154,125.805 62.479,126.13 62.663,126.13 63.201,126.667 63.201,132.622 60.408,135.415 59.579,135.415 R63.2@59.34,135.654
NetC52_1: C52.1 R57.1 R66.2 U5.12 | length 50.1
  Top Layer w0.3: C52.1@51.067,123.717 R57.1@51.067,122.192 51.368,122.494 53.101,122.494 53.147,122.447 54.276,122.447 54.539,122.184 v1(54.593,122.184) ; v1(55.434,114.849) 55.434,114.446 56.332,113.547 65.058,113.547 69.395,117.885 69.395,129.69 70.942,131.237 74.442,131.237 76.306,133.102 R66.2@76.706,133.102
  Bottom Layer w0.3: v1(54.593,122.184) 55.434,121.344 v1(55.434,114.849)
NetC56_1: C56.1 R67.1 R79.1 U5.1 | length 4.9
  Top Layer w0.3: U5.1@58.551,119.954 58.644,119.954 58.782,119.815 R79.1@58.782,118.339 ; C56.1@58.782,116.806 R79.1@58.782,118.339 ; R67.1@60.376,118.339 R79.1@58.782,118.339
NetC56_2: C56.2 R72.2 R79.2 U5.2 | length 34.1
  Top Layer w0.3: U5.2@58.551,121.224 58.493,121.166 57.463,121.166 57.107,120.811 57.107,118.414 R79.2@57.182,118.339 C56.2@57.182,116.806 57.182,115.977 58.371,114.788 64.381,114.788 68.201,118.607 R72.2@68.201,133.123
NetC57_1: C57.1 R68.1 R80.1 U5.7 | length 6.1
  Top Layer w0.3: U5.7@58.551,127.574 58.914,127.574 59.745,128.405 59.745,129.266 60.07,129.591 C57.1@60.095,129.591 R80.1@60.095,131.237 R68.1@60.095,132.827
NetC57_2: C57.2 R75.2 R80.2 U5.6 | length 12.9
  Top Layer w0.3: R75.2@54.995,135.66 54.995,134.498 57.93,131.562 58.17,131.562 R80.2@58.495,131.237 C57.2@58.495,129.591 58.17,129.266 57.68,129.266 57.182,128.768 57.182,126.723 57.544,126.361 58.493,126.361 U5.6@58.551,126.304
NetC58_1: C58.1 R69.1 R81.1 U5.14 | length 4.9
  Top Layer w0.3: C58.1@49.389,119.032 C58.1@49.395,119.038 R81.1@50.842,119.038 ; R81.1@51.098,119.154 51.217,119.272 52.076,119.272 ; R69.1@52.268,118.263 52.268,119.079 52.076,119.272 ; U5.14@53.101,119.954 52.757,119.954 52.076,119.272
NetC58_2: C58.2 R78.2 R81.2 U5.13 | length 42.6
  Top Layer w0.3: C58.2@49.395,120.638 R81.2@50.842,120.638 ; R81.2@51.098,120.754 52.125,120.754 52.595,121.224 53.101,121.224 53.158,121.166 53.898,121.166 54.995,120.069 54.995,116.426 57.205,114.215 64.78,114.215 68.783,118.219 68.783,130.204 71.375,132.795 71.836,132.795 R78.2@72.136,133.095
NetC59_2: C59.2 R82.1 R84.1 U4.12 | length 5.2
  Top Layer w0.3: C59.2@64.406,86.681 R82.1@64.406,85.05 64.415,85.04 R84.1@65.904,85.04 65.904,84.09 65.384,83.57 U4.12@65.384,83.168
NetC60_2: C60.2 R83.1 R85.1 U4.10 | length 5.2
  Top Layer w0.3: U4.10@67.924,83.168 67.924,84.697 67.589,85.032 R85.1@67.589,85.057 R83.1@69.22,85.057 C60.2@70.714,85.057
NetC63_1: C63.1 R88.1 R90.2 U4.13 | length 7.4
  Top Layer w0.3: R88.1@58.222,81.263 58.225,81.261 R90.2@59.678,81.261 59.685,81.267 C63.1@61.204,81.267 63.43,81.267 64.114,81.951 U4.13@64.114,83.168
